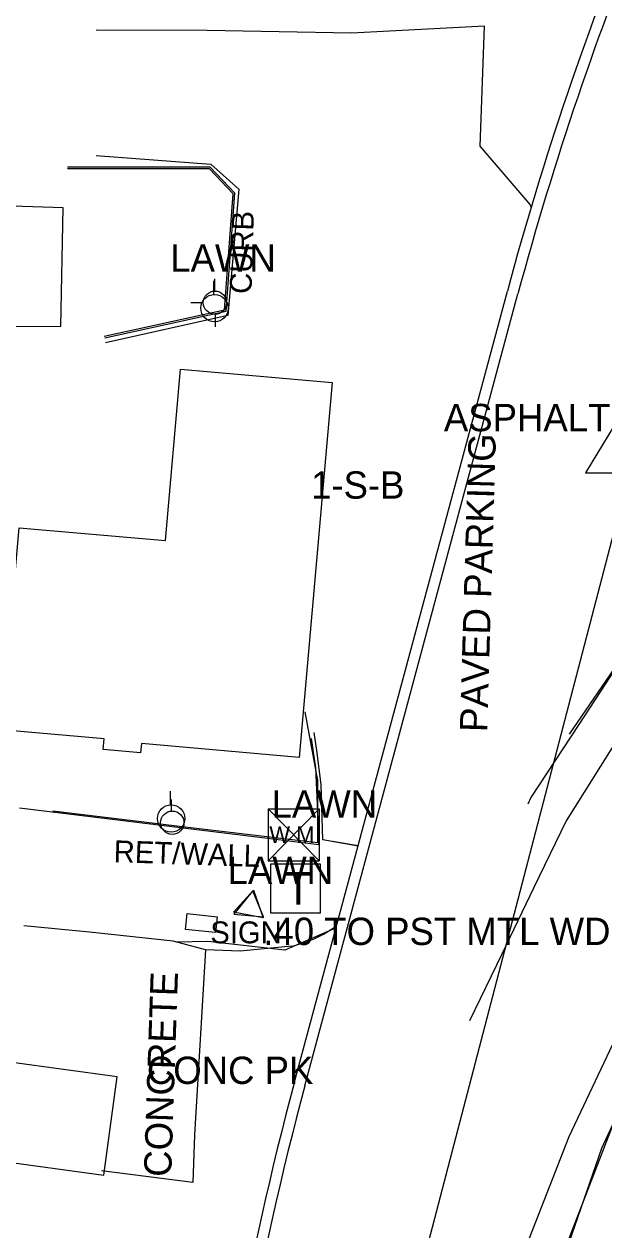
# Model space of a CAD drawing. Extents: x 978516 to 993312, y 1836504 to 1846212.
# Drawn here: x 992580.2 to 992686.2, y 1840378.8 to 1840599.3 of the extents above; entities that cross this region are included whole.
import ezdxf

# ---------------------------------------------------------------- set-up
doc = ezdxf.new("R2010")
doc.units = 0
for name, color, linetype in [('R_MOT Stage 1 Widening', 7, 'Continuous'), ('S_BASELINE', 7, 'Continuous'), ('S_BUILDING', 7, 'Continuous'), ('S_CURB', 7, 'Continuous'), ('S_CURB_ANNOT', 7, 'Continuous'), ('S_DRIVEWAY', 7, 'Continuous'), ('S_EDGE_PAVEMENT', 7, 'Continuous'), ('S_IRON_PIN_ANNOT', 7, 'Continuous'), ('S_LANDSCAPING', 7, 'Continuous'), ('S_PARKING_ANNOT', 7, 'Continuous'), ('S_PRIMARY_CTL', 7, 'Continuous'), ('S_SHOULDER', 7, 'Continuous'), ('S_SIDEWALK', 7, 'Continuous'), ('S_SIGN', 7, 'Continuous'), ('S_SIGN_ANNOT', 7, 'Continuous'), ('S_SURVEY_TEXT_ANNOT', 7, 'Continuous'), ('S_TELEPHONE_UTILITIES', 7, 'Continuous'), ('S_UTILITY_POLE', 7, 'Continuous'), ('S_WALL', 7, 'Continuous'), ('S_WATER_UTILITIES', 7, 'Continuous')]:
    doc.layers.add(name, color=color, linetype=linetype)

msp = doc.modelspace()

# ---------------------------------------------------------------- linework, layer by layer
at = {"layer": 'R_MOT Stage 1 Widening'}
for p, q in [((992629.61, 1840405.63), (992668.59, 1840550.48)), ((992631.54, 1840405.11), (992670.52, 1840549.96))]:
    msp.add_line(p, q, dxfattribs=at)
for centre, radius, start, end in [((993234.41, 1840398.18), 585.96, 157.55254, 164.93538), ((993234.41, 1840398.18), 583.96, 157.55254, 164.93538), ((993195.43, 1840253.34), 585.96, 164.93538, 174.67007), ((993195.43, 1840253.34), 583.96, 164.93538, 174.67007)]:
    msp.add_arc(centre, radius, start, end, dxfattribs=at)
at = {"layer": 'S_BASELINE'}
msp.add_line((992692.91, 1840525.06), (992469.46, 1839669.75), dxfattribs=at)
at = {"layer": 'S_BUILDING'}
for points in [[(992636.53, 1840533.75), (992630.51, 1840465.19), (992601.62, 1840467.73), (992601.47, 1840466.03), (992594.64, 1840466.63), (992594.8, 1840468.56), (992576.03, 1840470.21), (992579.28, 1840507.19), (992606.03, 1840504.84), (992608.79, 1840536.19)], [(992575.1, 1840391.49), (992594.77, 1840388.82), (992597.21, 1840406.75), (992577.53, 1840409.43)]]:
    msp.add_lwpolyline(points, close=True, dxfattribs=at)
at = {"layer": 'S_CURB'}
for points in [[(992594.91, 1840541.91), (992617.12, 1840546.82), (992618.74, 1840568.38), (992614.23, 1840573.1), (992601.17, 1840573.11), (992588.1, 1840573.12)], [(992594.84, 1840542.2), (992616.84, 1840547.06), (992618.44, 1840568.27), (992614.1, 1840572.8), (992601.1, 1840572.81), (992588.1, 1840572.82)]]:
    msp.add_lwpolyline(points, dxfattribs=at)
at = {"layer": 'S_DRIVEWAY'}
for points in [[(992672.97, 1840565.84), (992672.77, 1840566.31), (992663.61, 1840576.95), (992664.38, 1840598.94), (992640.06, 1840597.65), (992626.86, 1840597.9), (992613.66, 1840598.15), (992593.34, 1840598.21)], [(992593.36, 1840575.26), (992614.35, 1840573.7), (992619.46, 1840569.1), (992617.45, 1840546.01), (992595.06, 1840541)], [(992641.26, 1840448.94), (992634.81, 1840450.09), (992634.51, 1840460.26), (992633.72, 1840466.46), (992633.25, 1840469.75)], [(992636.6, 1840449.88), (992641.29, 1840449.06)], [(992629.18, 1840430.69), (992619.69, 1840429.75), (992613.36, 1840429.97), (992607.47, 1840431.57), (992592.11, 1840433.24), (992580.11, 1840434.37)], [(992637.24, 1840434), (992627.85, 1840429.91), (992613.77, 1840431.52), (992608.14, 1840431.37)], [(992613.36, 1840429.97), (992611.33, 1840396.15), (992611.04, 1840387.45), (992594.31, 1840389.58)]]:
    msp.add_lwpolyline(points, dxfattribs=at)
msp.add_ellipse((992624.4, 1840452.04), major_axis=(21.71, -2.8), ratio=0.999474, start_param=5.06072, end_param=5.473484, dxfattribs=at)
at = {"layer": 'S_EDGE_PAVEMENT'}
for points in [[(992727.17, 1840479.58), (992723.79, 1840499.26), (992721.4, 1840518.33), (992709.95, 1840501.18), (992698.5, 1840484.04), (992688.92, 1840468.82), (992679.35, 1840453.6), (992673.45, 1840441.41), (992667.56, 1840429.21), (992661.66, 1840417.01)], [(992727.17, 1840479.52), (992720.19, 1840471.32), (992710.13, 1840454.97), (992700.07, 1840438.61), (992689.95, 1840417.21), (992679.83, 1840395.82), (992671.68, 1840374.91)]]:
    msp.add_lwpolyline(points, dxfattribs=at)
at = {"layer": 'S_IRON_PIN_ANNOT'}
msp.add_lwpolyline([(992579.34, 1840455.99), (992620.27, 1840450.94), (992634.1, 1840449.24), (992634, 1840453.88), (992633.53, 1840463.29), (992632.75, 1840468.64)], dxfattribs=at)
at = {"layer": 'S_PRIMARY_CTL'}
for p, q in [((992692.91, 1840533.76), (992682.88, 1840517.25)), ((992682.88, 1840517.25), (992702.74, 1840517.25))]:
    msp.add_line(p, q, dxfattribs=at)
at = {"layer": 'S_SHOULDER'}
for points in [[(992679.93, 1840469.45), (992694.86, 1840491.14), (992712.59, 1840511.13), (992721.74, 1840519.04)], [(992718.52, 1840514.78), (992710.74, 1840509.48), (992699.21, 1840495.89), (992690.4, 1840484.57), (992681.65, 1840471.21), (992672.91, 1840457.84), (992672.34, 1840456.65)], [(992721.59, 1840470.99), (992713.92, 1840454.4), (992706.25, 1840437.82), (992696.04, 1840415.74), (992685.83, 1840393.66), (992678.72, 1840373.27)], [(992717.38, 1840464.52), (992710.22, 1840449.16), (992701.13, 1840426.2), (992689.81, 1840403.05), (992677.84, 1840371.95), (992667.61, 1840339.8), (992652.64, 1840298.18), (992643.63, 1840265.47), (992625.17, 1840202.99), (992614.29, 1840160.82), (992602.66, 1840116.12)]]:
    msp.add_lwpolyline(points, dxfattribs=at)
at = {"layer": 'S_SIDEWALK'}
msp.add_lwpolyline([(992577.25, 1840536.24), (992577.34, 1840544.08), (992586.89, 1840544.01), (992587.29, 1840565.7), (992578.06, 1840565.98), (992578.02, 1840573.24)], dxfattribs=at)
msp.add_lwpolyline([(992610.02, 1840436.67), (992615.5, 1840436.06), (992615.18, 1840433.14), (992609.7, 1840433.74)], close=True, dxfattribs=at)
at = {"layer": 'S_SIGN'}
for p, q in [((992618.5, 1840436.89), (992622.12, 1840440.94)), ((992622.12, 1840440.94), (992623.93, 1840435.88)), ((992623.93, 1840435.88), (992618.5, 1840436.89))]:
    msp.add_line(p, q, dxfattribs=at)
msp.add_lwpolyline([(992621.9, 1840440.69), (992618.57, 1840436.54), (992623.99, 1840436.05), (992622.07, 1840440.6)], dxfattribs=at)
at = {"layer": 'S_TELEPHONE_UTILITIES'}
msp.add_lwpolyline([(992625.34, 1840436.73), (992625.34, 1840445.73), (992634.34, 1840445.73), (992634.34, 1840436.73)], close=True, dxfattribs=at)
at = {"layer": 'S_UTILITY_POLE'}
for p, q in [((992614.88, 1840549.88), (992614.88, 1840552.36)), ((992615.09, 1840550.46), (992615.09, 1840552.7)), ((992613, 1840548.33), (992610.67, 1840548.33)), ((992615.17, 1840543.91), (992615.17, 1840546.23)), ((992606.93, 1840456.54), (992606.93, 1840459.02)), ((992607.16, 1840455.39), (992607.16, 1840457.5))]:
    msp.add_line(p, q, dxfattribs=at)
for centre, radius in [((992615.02, 1840547.36), 2.5), ((992615.09, 1840548.35), 2.13), ((992607.08, 1840454.02), 2.5), ((992607.28, 1840453.25), 2.13)]:
    msp.add_circle(centre, radius, dxfattribs=at)
at = {"layer": 'S_WALL'}
msp.add_lwpolyline([(992631.53, 1840473.5), (992633.83, 1840460.98), (992633.85, 1840449.57), (992609.64, 1840452.45), (992585.44, 1840455.33)], dxfattribs=at)
at = {"layer": 'S_WATER_UTILITIES'}
for p, q in [((992624.83, 1840455.8), (992634.17, 1840455.8)), ((992624.83, 1840455.8), (992624.83, 1840446.3)), ((992624.83, 1840455.8), (992634.17, 1840446.3)), ((992634.17, 1840455.8), (992624.83, 1840446.3)), ((992634.17, 1840455.8), (992634.17, 1840446.3)), ((992624.83, 1840446.3), (992634.17, 1840446.3))]:
    msp.add_line(p, q, dxfattribs=at)

# ---------------------------------------------------------------- texts
at = {"layer": 'S_CURB_ANNOT'}
msp.add_text('CURB', height=4, rotation=88.2942, dxfattribs=at).set_placement((992621.77, 1840549.91))
at = {"layer": 'S_LANDSCAPING'}
msp.add_text('RET/WALL', height=4, rotation=358.0701, dxfattribs=at).set_placement((992596.51, 1840446.04))
at = {"layer": 'S_PARKING_ANNOT'}
for s, height, rotation, p in [('PAVED PARKING', 5.0005, 88.2942, (992664.88, 1840469.77)), ('CONCRETE', 5, 88.0701, (992607.07, 1840388.42))]:
    msp.add_text(s, height=height, rotation=rotation, dxfattribs=at).set_placement(p)
at = {"layer": 'S_SIGN_ANNOT'}
for s, height, p in [('SIGN', 4, (992614.24, 1840431.19)), ('.40 TO PST MTL WD PAWN', 5, (992623.93, 1840430.88))]:
    msp.add_text(s, height=height, dxfattribs=at).set_placement(p)
at = {"layer": 'S_SURVEY_TEXT_ANNOT'}
for s, p in [('LAWN', (992606.91, 1840554.02)), ('ASPHALT', (992656.97, 1840524.84)), ('1-S-B', (992632.67, 1840512.5)), ('LAWN', (992625.45, 1840454.18)), ('LAWN', (992617.4, 1840442.06)), ('CONC PK', (992602.63, 1840405.47))]:
    msp.add_text(s, height=5, dxfattribs=at).set_placement(p)
at = {"layer": 'S_TELEPHONE_UTILITIES'}
msp.add_text('T', height=6, dxfattribs=at).set_placement((992627.9, 1840438.23))
at = {"layer": 'S_WATER_UTILITIES'}
msp.add_text('W M', height=3, dxfattribs=at).set_placement((992625.04, 1840449.56))

doc.saveas('drawing.dxf')
